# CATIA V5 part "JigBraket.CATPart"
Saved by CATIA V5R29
Part number: JigBraket
Bounding box of the stored display mesh (mm): x -25 to 25, y -30 to 30, z -50 to 15
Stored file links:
  C:\Users\Administrator\Desktop\프로젝트\Boxfold\JigBraket.CATPart
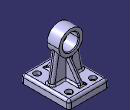
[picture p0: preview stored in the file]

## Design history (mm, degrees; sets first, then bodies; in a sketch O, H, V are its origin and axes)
Body1 (main body)
  DatumCurve1
  Sketch1 on zx-plane, origin (0, 0, 0), H (-1, 0, 0), V (0, 0, 1)
    circle A1 centre (0, 0) radius 10
    reference projected circle E1 centre (0, 0) radius 10 from edge of DatumCurve1
    circle A2 centre (0, 0) radius 15
    radius A2 = 15
    coincidence: A1 E1
  Pad1: profile Sketch1, direction (0, 1, 0), length 7.5, mirrored extent
  Chamfer1: length 1, angle 45, on edge [end face of Pad1 | face of Pad1 from Sketch1.A1]; edge [face of Pad1 from Sketch1.A1 | start face of Pad1]
  Plane1: type Offset, RefPlane xy-plane, Offset 50, reversed
  Sketch2 on Plane1, origin (0, 0, -50), H (1, 0, 0), V (0, 1, 0)
    line L1 (25, 30) -> (25, -30)
    line L2 (25, -30) -> (-25, -30)
    line L3 (-25, -30) -> (-25, 30)
    line L4 (-25, 30) -> (25, 30)
    distance L4 L2 = 60
    distance L1 L3 = 50
    vertical: L1 V, L3 V
    horizontal: L2 H, L4 H
    equidistance: L1 L3 O, L2 L4 O
  Pad2: profile Sketch2, direction (0, 0, 1), length 10
  Sketch3 on zx-plane, origin (0, 0, 0), H (-1, 0, 0), V (0, 0, 1)
    point P1 (-20, -40)
    line L1 (-20, -40) -> (-13.9286, -5.5673)
    arc A1 centre (0, 0) radius 15 from (-13.9286, -5.5673) to (13.9286, -5.5673) ccw
    line L2 (13.9286, -5.5673) -> (20, -40)
    point P5 (20, -40)
    line L3 (20, -40) -> (-20, -40)
    reference projected line E1 (-25, -40) -> (25, -40) from edge [face of Pad2 from Sketch2.L4 | end face of Pad2]
    reference projected line E2 (-25, -50) -> (-25, -40) from edge [face of Pad2 from Sketch2.L4 | face of Pad2 from Sketch2.L1]
    reference projected line E3 (-25, -50) -> (-25, -40) from edge [face of Pad2 from Sketch2.L4 | face of Pad2 from Sketch2.L1]
    reference projected circle E4 centre (0, 0) radius 15 from edge [face of Pad1 from Sketch1.A2 | end face of Pad1]
    reference projected line E5 (25, -50) -> (25, -40) from edge [face of Pad2 from Sketch2.L3 | face of Pad2 from Sketch2.L4]
    reference projected line E6 (25, -50) -> (25, -40) from edge [face of Pad2 from Sketch2.L3 | face of Pad2 from Sketch2.L4]
    angle L1 E2 = 10
    distance P1 E3 = 5
    angle L2 E5 = 10
    distance P5 E6 = 5
    coincidence: L3 E1, A1 E4
  Pad3: profile Sketch3, direction (0, 1, 0), length 4, mirrored extent
  Sketch4 on yz-plane, origin (0, 0, 0), H (0, 1, 0), V (0, 0, 1)
    point P1 (-5, -15)
    line L1 (-5, -15) -> (-22, -40)
    point P2 (-22, -40)
    reference projected line E1 (-30, -50) -> (-30, -40) from edge [face of Pad2 from Sketch2.L1 | face of Pad2 from Sketch2.L2]
    reference projected line E2 (-30, -40) -> (30, -40) from edge [face of Pad2 from Sketch2.L1 | end face of Pad2]
    reference intersected line E3 (-4, -15) -> (-7.5, -15) from face of Pad1 from Sketch1.A2
    reference projected line E6 (-4, -5.5673) -> (-4, -40) from edge [start face of Pad3 | face of Pad3 from Sketch3.L1]
    distance P2 E1 = 8
    distance P1 E6 = 1
    coincidence: P2 E2, P1 E3
  Stiffener1: ExtendedProfile Sketch4, ThicknessTop 0, ThicknessValue 6
  Mirror1: of Stiffener1, about zx-plane
  Fillet1: radius 3, on edge [face of Pad3 from Sketch3.L1 | end face of Pad3]; edge [start face of Pad3 | face of Pad3 from Sketch3.L1]; edge [face of Pad3 from Sketch3.L2 | end face of Pad3]; edge [start face of Pad3 | face of Pad3 from Sketch3.L2]; edge [face of Pad2 from Sketch2.L3 | end face of Pad2]; edge [face of Pad2 from Sketch2.L4 | end face of Pad2]; edge [face of Pad2 from Sketch2.L1 | end face of Pad2]; edge [face of Pad2 from Sketch2.L2 | end face of Pad2]; edge [face of Pad2 from Sketch2.L1 | face of Pad2 from Sketch2.L2]; edge [face of Pad2 from Sketch2.L4 | face of Pad2 from Sketch2.L1]; edge [face of Pad2 from Sketch2.L3 | face of Pad2 from Sketch2.L4]; edge [face of Pad2 from Sketch2.L2 | face of Pad2 from Sketch2.L3]
  Fillet2: radius 2, on edge [face of Stiffener1 | start face of Pad3]; edge [start face of Pad3 | face of Stiffener1]; edge [face of Stiffener1 | end face of Pad2]; edge [start face of Pad3 | end face of Pad2] (x2); edge [end face of Pad2 | face of Stiffener1] (x2); edge [face of Mirror1 | end face of Pad3]; edge [face of Mirror1 | end face of Pad2] (x2); edge [end face of Pad2 | face of Mirror1]
  Fillet3: radius 1, on edge [face of Stiffener1 | face of Pad1 from Sketch1.A2]; edge [face of Pad1 from Sketch1.A2 | face of Mirror1]
  Fillet4: radius 2, on edge [face of Mirror1 | face of Mirror1] (x2); edge [face of Stiffener1 | face of Stiffener1] (x2)
  Sketch5 on end face of Pad2, origin (13.8524, 19.3247, -40), H (1, 0, 0), V (0, 1, 0)
    point P1 (1.1476, 0.6753)
    reference projected line E1 (11.1476, -49.3247) -> (11.1476, 10.6753) from edge [face of Pad2 from Sketch2.L1 | end face of Pad2]
    reference projected line E2 (11.1476, 10.6753) -> (-38.8524, 10.6753) from edge [face of Pad2 from Sketch2.L4 | end face of Pad2]
    distance P1 E1 = 10
    distance P1 E2 = 10
  Hole1: placed by Sketch5, at (15, 20, -40) direction (0, 0, -1), diameter 4.5, through (limit type 3), counterbore diameter 8, counterbore depth 4.4
  RectPattern1: of Hole1, direction 1 instances 2, spacing 30, along edge [face of Fillet1 | end face of Pad2], direction 2 instances 2, spacing 40, along edge [face of Fillet1 | end face of Pad2] reversed
  Plane2: stored without definition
